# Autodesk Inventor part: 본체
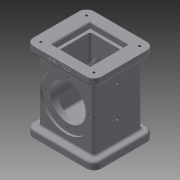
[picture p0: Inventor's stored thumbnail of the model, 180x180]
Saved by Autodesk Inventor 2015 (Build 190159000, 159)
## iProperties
Created: 2017-08
Part Number: 본체
Material: 일반
Document SubType Name: Modeling
Designer: Administrator
Density: 1 g/cm^3
Appearance: 기본값
Author: Administrator
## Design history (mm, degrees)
sketch "스케치1"
  geometry: L1 (-46, 41)-(46, 41); L2 (46, 41)-(46, -41); L3 (46, -41)-(-46, -41); L4 (-46, -41)-(-46, 41); L5 (-46, 41)-(46, -41); 2 further points
  constraints: 10 end point, 2 parallel, 1 coincident, 1 horizontal, 1 midpoint, 1 perpendicular
  dimensions: "d0" = 92 distance of L2.end L3.end; "d1" = 82 distance of L1.end L2.end
extrude "돌출1" new body sketch "스케치1" distance "d2" = 10; taper "d3" = 0 deg
sketch "스케치2"
  geometry: L1 (37, -33)-(-37, -33); L2 (-37, -33)-(-37, 33); L3 (-37, 33)-(37, 33); L4 (37, 33)-(37, -33); L5 (37, -33)-(-37, 33); 2 further points
  constraints: 10 end point, 2 parallel, 1 coincident, 1 horizontal, 1 midpoint, 1 perpendicular
  dimensions: "d4" = 74 distance of L1.start L1.end; "d5" = 66 distance of L1.end L2.end
extrude "돌출2" join sketch "스케치2" distance "d6" = 88; taper "d7" = 0 deg
sketch "스케치3"
  geometry: L1 (46, -41)-(-46, -41); L2 (-46, -41)-(-46, 41); L3 (-46, 41)-(46, 41); L4 (46, 41)-(46, -41); 1 further point
  constraints: 8 end point, 2 parallel, 1 horizontal, 1 perpendicular
extrude "돌출3" join sketch "스케치3" distance "d8" = 10; taper "d9" = 0 deg
sketch "스케치5"
  geometry: L1 (54, -56.881)-(54, 67.394); L2 (10, -33)-(98, -33) reference; L3 (10, 33)-(98, 33) reference; L4 (54, -33)-(89, -33); L5 (89, -30)-(89, -33); L6 (89, -30)-(78, -30); L7 (78, -30)-(78, 30); L8 (78, 30)-(89, 30); L9 (89, 30)-(89, 33); L10 (89, 33)-(54, 33); L11 (54, -33)-(54, 33); 1 further point
  constraints: 18 end point, 5 perpendicular, 2 midpoint, 2 point on line, 1 horizontal, 1 vertical
  dimensions: "d15" = 54 distance from line of point (0, 0) L1; "d16" = 70 diameter of L5 L1; "d17" = 48 diameter of L7 L1; "d18" = 3 distance of L5.start L4.end; "d19" = 70 diameter of L9 L1; "d20" = 3 distance of L8.end L9.end
revolve "회전1" sketch "스케치5" stored, may be unused: angle "d21" = 90 deg
sketch "스케치6"
  geometry: L1 (-24, -24)-(24, -24); L2 (24, -24)-(24, 24); L3 (24, 24)-(-24, 24); L4 (-24, 24)-(-24, -24); L5 (-24, -24)-(24, 24); 2 further points
  constraints: 10 end point, 2 parallel, 1 coincident, 1 horizontal, 1 midpoint, 1 perpendicular
  dimensions: "d22" = 48 distance of L1.end L2.end; "d23" = 48 distance of L2.end L3.end
extrude "돌출4" cut sketch "스케치6" distance "d24" = 16; taper "d25" = 0 deg
sketch "스케치7"
  geometry: L1 (26, 26)-(-26, 26); L2 (-26, 26)-(-26, -26); L3 (-26, -26)-(26, -26); L4 (26, -26)-(26, 26); L5 (26, 26)-(-26, -26); 2 further points
  constraints: 10 end point, 2 parallel, 1 coincident, 1 horizontal, 1 midpoint, 1 perpendicular
  dimensions: "d26" = 52 distance of L3.end L1.start; "d27" = 52 distance of L2.end L3.end
extrude "돌출5" cut sketch "스케치7" distance "d28" = 8; taper "d29" = 0 deg
sketch "스케치8"
  geometry: L1 (22, 22)-(-22, 22); L2 (-22, 22)-(-22, -22); L3 (-22, -22)-(22, -22); L4 (22, -22)-(22, 22); L5 (22, 22)-(-22, -22); 2 further points
  constraints: 10 end point, 2 parallel, 1 coincident, 1 horizontal, 1 midpoint, 1 perpendicular
  dimensions: "d30" = 44 distance of L1.end L2.end; "d31" = 44 distance of L2.end L3.end
extrude "돌출6" cut sketch "스케치8" distance "d32" = 74; taper "d33" = 0 deg
sketch "스케치9" dims "d34" = 58
  geometry: L1 (0, 0)-(0, 41.751); C1 r 35 at (0, 0) reference; 5 further points
  constraints: 2 end point, 1 coincident, 1 point on line, 1 vertical, 1 vertical alignment, 7 other
  dimensions: "d37" = 360 deg dimension on L1.start point (0, 29) (derived)
hole "구멍1" sketch "스케치9" at (0, 29), (-29, 0), (0, -29), (29, 0) diameter "d39" = 3.242; stored, may be unused: countersink angle "d43" = 90 deg, drill point angle "d45" = 118 deg; dims "d40" = 4, "d41" = 4, "d42" = 2, "d44" = 6
sketch "스케치10"
  geometry: 5 further points
  dimensions: "d48" = 72 distance of point (-36, -31) point (36, -31); "d49" = 36 horizontal distance of point (36, -31) point (0, 0); "d50" = 72 distance of point (36, 31) point (-36, 31); "d51" = 36 horizontal distance of point (0, 0) point (36, 31); "d52" = 62 distance of point (-36, -31) point (-36, 31); "d53" = 31 vertical distance of point (-36, 31) point (0, 0); "d54" = 62 distance of point (36, -31) point (36, 31); "d55" = 31 vertical distance of point (0, 0) point (36, 31)
hole "구멍2" sketch "스케치10" at (36, -31), (-36, -31), (36, 31), (-36, 31) diameter "d56" = 3.242; stored, may be unused: countersink angle "d60" = 90 deg, drill point angle "d62" = 118 deg; dims "d57" = 4, "d58" = 4, "d59" = 2, "d61" = 6
node "작업 평면1"
sketch "스케치11" dims "d15" = 54, "d16" = 70, "d17" = 48, "d18" = 3, "d19" = 70, "d20" = 3
  geometry: L1 (33, -10)-(33, 116.657); 2 further points
  constraints: 2 end point, 2 point on line, 1 vertical
  dimensions: "d64" = 38 distance of L1.start point (33, 28); "d65" = 42 distance of point (33, 28) point (33, 70)
hole "구멍3" sketch "스케치11" at (33, 28), (33, 70) diameter "d66" = 4.134; stored, may be unused: countersink angle "d70" = 90 deg, drill point angle "d72" = 118 deg; dims "d67" = 25, "d68" = 4, "d69" = 2, "d71" = 30
node "작업 평면2"
sketch "스케치12"
  geometry: L1 (92, 0)-(0, 0) reference; L2 (92, 0)-(92, 10) reference; L3 (0, 10)-(92, 10) reference; L4 (0, 0)-(0, 10) reference; L5 (0, 10.9)-(92.44, 10.9); L6 (92.44, 10.9)-(92.44, 1.1); L7 (92.44, 1.1)-(0, 1.1); L8 (0, 1.1)-(0, 10.9); L9 (46, -98)-(46, 36.846); L10 (0, 6)-(92.44, 6)
  constraints: 4 end point, 2 midpoint, 1 vertical, 2 other
  dimensions: "d74" = 4 distance between parallel lines of L3 L10; "d75" = 46 distance from line of L9 L5.start
feature "엠보싱1" sketch "스케치12" dims "d0" = 92, "d1" = 82, "d76" = 0.5, "d77" = 0
chamfer "모따기1" distance "d78" = 1; stored, may be unused: second distance "d79" = 2, angle "d80" = 45 deg
fillet "모깎기1" dims "d81" = 3
fillet "모깎기2" dims "d82" = 3
fillet "모깎기3" dims "d83" = 3
fillet "모깎기4" dims "d84" = 3
fillet "모깎기5" dims "d85" = 3
fillet "모깎기6" dims "d86" = 10
node "솔리드1"
mirror "대칭1"
mirror "대칭2"
node "투영된 루프1"
other parameters: "d63" = -54, "d73" = 0
